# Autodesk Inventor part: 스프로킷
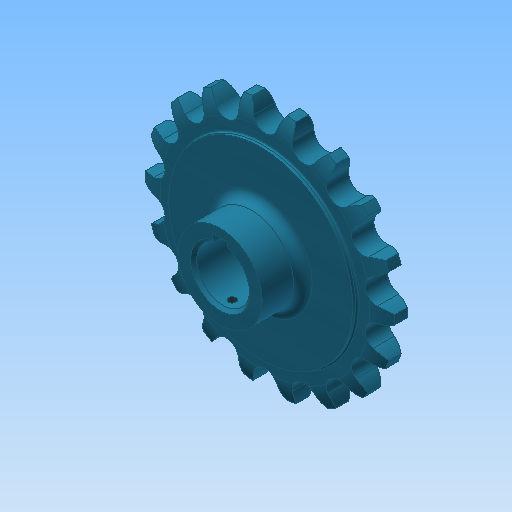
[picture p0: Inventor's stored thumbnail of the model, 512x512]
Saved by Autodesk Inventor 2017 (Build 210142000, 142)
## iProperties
Created: 2016-03
Part Number: 스프로킷
Material: 강철, 탄소
Document SubType Name: Modeling
Designer: mduedu
Density: 7.87 g/cm^3
Mass: 301.818 g
Surface Area: 124.882 cm^2
Volume: 38.3505 cm^3
Appearance: 터키옥색
Author: mduedu
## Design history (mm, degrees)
sketch "스케치1"
  geometry: L1 (0, 5)-(29.5, 5); L2 (29.5, 5)-(29.5, 4.1); L3 (30, 3.6)-(33.625, 3.6); L4 (40, 2)-(40, 0); L5 (40, 0)-(0, 0); L6 (0, 0)-(0, 5); L7 (0, -5)-(29.5, -5); L8 (29.5, -5)-(29.5, -4.1); L9 (30, -3.6)-(33.625, -3.6); L10 (40, -2)-(40, 0); L11 (0, 0)-(0, -5); A1 r 13.5 centre (33.625, -9.9) between (40, 2) and (33.625, 3.6); A2 r 13.5 centre (33.625, 9.9) between (33.625, -3.6) and (40, -2); A3 r 0.5 centre (30, 4.1) between (29.5, 4.1) and (30, 3.6); A4 r 0.5 centre (30, -4.1) between (30, -3.6) and (29.5, -4.1); 2 further points
  constraints: 22 end point, 8 point on circle, 6 symmetric about line, 5 tangent, 4 centre point, 4 parallel, 4 point on line, 1 equal radius, 1 horizontal, 1 perpendicular, 1 other
  dimensions: "d0" = 80 diameter of L4 L6; "d2" = 59 diameter of L2 L6; "d3" = 1.6 vertical distance of L4.start L3.end; "d4" = 3.6 distance from line of L4.end L3; "d5" = 5 distance between parallel lines of L5 L1; "d6" = 13.5 radius of A1; "d15" = 0.5 radius of A3
revolve "회전1" sketch "스케치1" stored, may be unused: angle "d7" = 90 deg
sketch "스케치2" dims "d8" = 65.2, "d11" = 80
  geometry: L1 (0, 0)-(0, 32.6); A1 r 36.57 centre (0, 0) between (-16.231, 32.771) and (0, 36.57); A2 r 3.97 centre (0, 36.57) between (-3.866, 35.665) and (0, 32.6); A3 r 12.7 centre (-16.231, 32.771) between (-3.866, 35.665) and (-5.534, 39.615); A4 r 12.7 centre (16.231, 32.771) between (5.534, 39.615) and (3.866, 35.665); A5 r 3.97 centre (0, 36.57) between (0, 32.6) and (3.866, 35.665); A6 r 40 centre (0, 0) between (5.534, 39.615) and (-5.534, 39.615); 2 further points
  constraints: 12 point on circle, 6 centre point, 4 coincident, 3 symmetric about line, 2 end point, 1 point on line, 1 tangent, 1 vertical, 1 vertical alignment, 7 other
  dimensions: "d10" = 73.14 diameter of A1; "d12" = 12.7 radius of A3
extrude "돌출1" cut sketch "스케치2" stored distance "d13" = 10; taper "d14" = 0 deg
sketch "스케치3"
  geometry: C1 r 13.5 at (0, 0); 1 further point
  constraints: 1 centre point, 1 coincident
  dimensions: "d19" = 27 diameter of C1
extrude "돌출2" join sketch "스케치3" distance "d20" = 13; taper "d21" = 0 deg
fillet "모깎기1" dims "d22" = 3
sketch "스케치4"
  geometry: L1 (-2.5, 0)-(2.5, 0); L2 (2.5, 0)-(2.5, 10.8); L3 (2.5, 10.8)-(-2.5, 10.8); L4 (-2.5, 10.8)-(-2.5, 0); C1 r 8.5 at (0, 0); 2 further points
  constraints: 8 end point, 2 coincident, 2 parallel, 1 centre point, 1 horizontal, 1 midpoint, 1 perpendicular
  dimensions: "d23" = 17 diameter of C1; "d25" = 5 distance of L2.end L3.end; "d26" = 10.8 distance of L1.end L2.end
extrude "돌출3" cut sketch "스케치4" stored distance "d27" = 8; taper "d28" = 0 deg
chamfer "모따기1" distance "d29" = 1; stored, may be unused: second distance "d30" = 2, angle "d31" = 45 deg
node "작업 평면1"
sketch "스케치5"
  geometry: L1 (13.5, 13)-(-13.5, 13) reference; 2 further points
  constraints: 1 vertical alignment
  dimensions: "d32" = 4 distance from line of point (0, 9) L1
hole "구멍1" sketch "스케치5" at (0, 9) diameter "d33" = 2.459; stored, may be unused: countersink angle "d37" = 90 deg, drill point angle "d39" = 118 deg; dims "d34" = 6, "d35" = 4, "d36" = 2, "d38" = 8
node "솔리드1"
pattern_circular "원형 패턴1" dims angle "d17" = 360 deg
